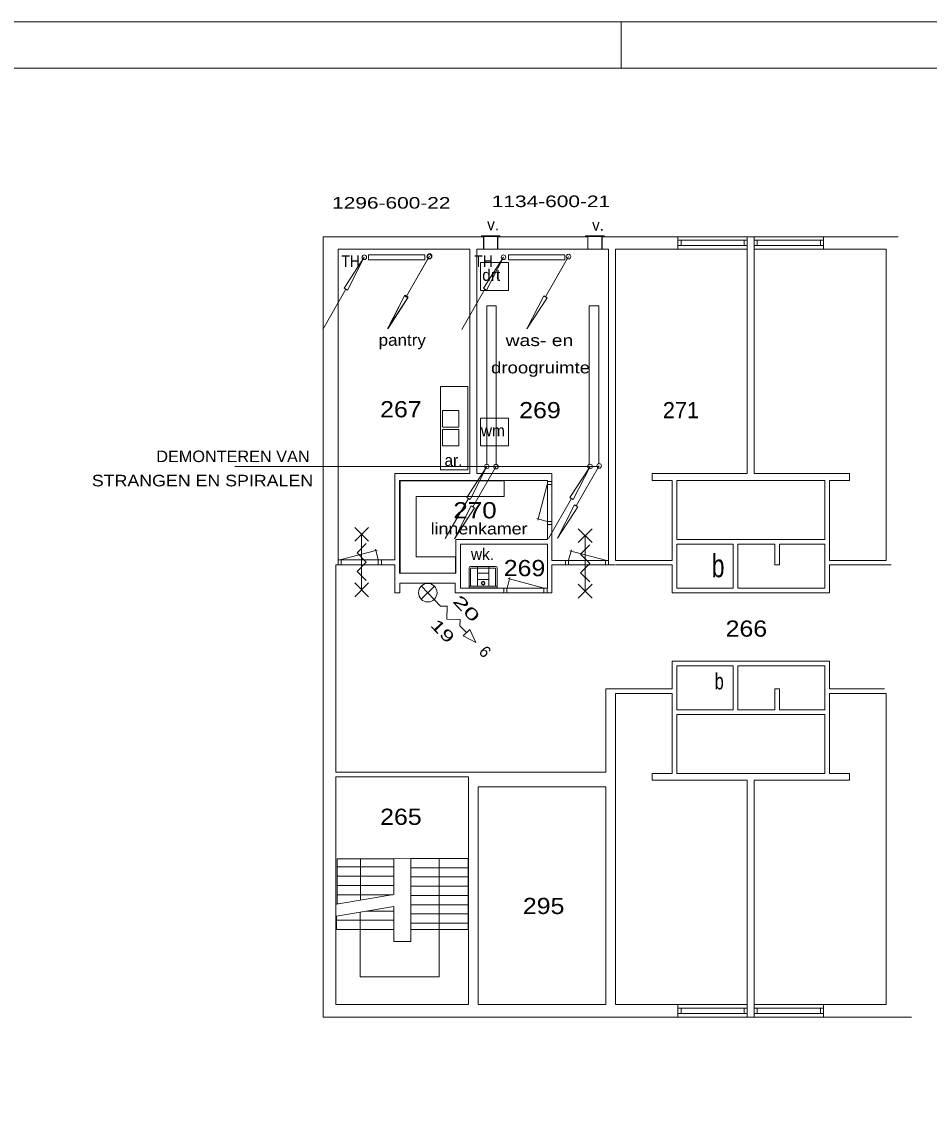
# Model space of a CAD drawing. Extents: x 295824 to 414724, y 24924 to 109024.
# Drawn here: x 338765 to 358386, y 85348 to 109024 of the extents above; entities that cross this region are included whole.
import ezdxf
from ezdxf.enums import TextEntityAlignment as Align

# ---------------------------------------------------------------- set-up
doc = ezdxf.new("R2010")
doc.units = 0
doc.header["$LTSCALE"] = 100
for name, color, linetype, lineweight in [('1', 7, 'Continuous', 13), ('16', 7, 'Continuous', 13), ('61', 7, 'Continuous', 13)]:
    doc.layers.add(name, color=color, linetype=linetype, lineweight=lineweight)

msp = doc.modelspace()

# ---------------------------------------------------------------- linework, layer by layer
at = {"layer": '1'}
msp.add_line((351723.6, 108023.8), (351723.6, 109023.8), dxfattribs=at)
for points in [[(414723.6, 109023.8), (304995.6, 109023.8), (295823.6, 109023.8)], [(304995.6, 25923.8), (413723.6, 25923.8), (413723.6, 108023.8), (304995.6, 108023.8)]]:
    msp.add_lwpolyline(points, dxfattribs=at)
at = {"layer": '16'}
for p, q in [((347576.1, 103948.9), (347076.1, 103082.9)), ((347582, 103960.7), (347082, 103094.7)), ((350586.2, 103948.9), (350086.2, 103082.9)), ((345270.5, 102377.2), (345770.5, 103243.2)), ((348280.7, 102377.2), (348780.7, 103243.2)), ((343368.4, 99410.3), (351252.5, 99410.3)), ((349017.9, 99408.9), (348517.9, 98542.9)), ((351249.9, 99425.5), (350749.9, 98559.5)), ((347920.8, 97854.5), (348420.8, 98720.5)), ((350152.8, 97854.5), (350652.8, 98720.5))]:
    msp.add_line(p, q, dxfattribs=at)
for points in [[(346170.5, 103936.2), (345806.5, 103222.2), (345734.5, 103264.2)], [(346260.1, 103883.5), (347476.8, 103883.5), (347476.8, 103990.7), (346260.1, 103990.7)], [(349180.7, 103936.2), (348816.7, 103222.2), (348744.7, 103264.2)], [(349287.8, 103883.5), (350504.5, 103883.5), (350504.5, 103990.7), (349287.8, 103990.7)], [(346676.1, 102389.9), (347040.1, 103103.9), (347112.1, 103061.9)], [(346682, 102401.7), (347046, 103115.7), (347118, 103073.7)], [(349686.2, 102389.9), (350050.2, 103103.9), (350122.2, 103061.9)], [(348820.8, 99413.5), (348456.8, 98699.5), (348384.8, 98741.5)], [(351052.8, 99413.5), (350688.8, 98699.5), (350616.8, 98741.5)], [(348117.9, 97849.9), (348481.9, 98563.9), (348553.9, 98521.9)], [(350349.9, 97866.5), (350713.9, 98580.5), (350785.9, 98538.5)]]:
    msp.add_lwpolyline(points, close=True, dxfattribs=at)
for points in [[(348821.9, 99450.9), (348821.9, 102882.9), (349024.4, 102882.9), (349024.4, 99462.8)], [(351037.1, 99450.9), (351037.1, 102882.9), (351239.5, 102882.9), (351239.5, 99462.8)]]:
    msp.add_lwpolyline(points, dxfattribs=at)
for centre in [(346170.5, 103935.8), (347576.1, 103949.2), (347582, 103961), (349180.7, 103935.8), (350586.2, 103949.2), (348820.8, 99413.2), (349017.9, 99409.2), (351052.8, 99413.2), (351249.9, 99425.8)]:
    msp.add_circle(centre, 50, dxfattribs=at)
at = {"layer": '61'}
for p, q in [((345284, 104378.8), (345284, 87509.4)), ((345654, 104378.8), (345284, 104378.8)), ((345284, 104378.8), (348747.5, 104378.8)), ((349101.1, 104400.3), (348702.8, 104400.3)), ((348702.8, 104400.3), (348702.8, 104385.2)), ((349101.1, 104385.2), (348702.8, 104385.2)), ((348747.5, 104378.8), (348747.5, 104110.1)), ((348753.1, 104385.2), (348753.1, 104110.9)), ((349051.8, 104385.2), (349051.8, 104110.9)), ((349058.2, 104378.8), (349058.2, 104110.4)), ((349058.2, 104378.8), (351001.2, 104378.8)), ((349101.1, 104400.3), (349101.1, 104385.2)), ((351354.8, 104400.3), (350956.5, 104400.3)), ((350956.5, 104400.3), (350956.5, 104385.2)), ((351354.8, 104385.2), (350956.5, 104385.2)), ((351001.2, 104378.8), (351001.2, 104110.4)), ((351006.8, 104385.2), (351006.8, 104110.9)), ((351305.5, 104385.2), (351305.5, 104110.9)), ((351311.9, 104378.8), (351311.9, 104108.8)), ((351311.9, 104378.8), (357714.4, 104378.8)), ((351354.8, 104400.3), (351354.8, 104385.2)), ((352953.9, 104111.8), (352953.9, 104381.8)), ((353020.7, 104190.1), (353020.7, 104303.9)), ((354385.7, 104189.5), (354385.7, 104303.5)), ((354669.2, 104190.4), (354669.2, 104304.4)), ((356033.5, 104190.1), (356033.5, 104303.8)), ((356102, 104111.8), (356102, 104382)), ((345604, 97284), (345604, 104108.8)), ((348604, 104110.1), (348747.5, 104110.1)), ((351454, 104108.8), (348604, 104108.8)), ((349051.8, 104110.9), (348753.1, 104110.9)), ((349058.2, 104110.4), (349204, 104110.4)), ((350854.5, 104110.4), (351001.2, 104110.4)), ((351305.5, 104110.9), (351006.8, 104110.9)), ((351604, 104108.8), (354454, 104108.8)), ((357454, 104108.8), (354604, 104108.8)), ((347864.1, 100620.5), (348214.1, 100620.5)), ((348215, 100618.8), (348215, 100268.8)), ((348214.1, 100266.4), (347864.1, 100266.4)), ((347864.1, 100212.3), (348214.1, 100212.3)), ((348215, 100210.6), (348215, 99860.6)), ((348214.1, 99858.2), (347864.1, 99858.2)), ((346929, 97103.8), (346929, 99108.8)), ((350127, 99024.6), (349919.9, 98251.8)), ((350228.5, 99090.8), (350127.6, 99090.8)), ((350226.5, 99023.8), (350128.9, 99023.8)), ((350226.9, 99090.8), (350130.2, 99090.8)), ((350126.4, 98226.2), (349899.5, 98286.9)), ((346262.8, 98096.2), (345962.8, 97796.2)), ((345962.8, 98096.2), (346262.8, 97796.2)), ((350226.2, 98223.8), (350127.6, 98223.8)), ((350226.5, 98156.8), (350127.6, 98156.8)), ((351099, 98066.6), (350799, 97766.6)), ((350799, 98066.6), (351099, 97766.6)), ((346112.8, 96746.2), (346112.8, 97946.2)), ((350949, 96716.6), (350949, 97916.6)), ((345672.2, 97398.6), (346444.9, 97605.7)), ((346470.6, 97399.3), (346409.8, 97626.1)), ((350588.1, 97384.9), (350648.9, 97611.8)), ((351386.5, 97384.3), (350613.8, 97591.3)), ((345673, 97284), (345673, 97398)), ((346473, 97284), (346473, 97398)), ((346540, 97284), (346540, 97398)), ((350518.8, 97284.8), (350518.8, 97383.7)), ((350585.8, 97285), (350585.8, 97383.7)), ((351385.8, 97284.8), (351385.8, 97383.7)), ((351452.8, 97284.8), (351452.8, 97383.7)), ((345554, 97284), (345604, 97284)), ((346829, 96683.8), (346829, 97284)), ((348149, 97103.8), (346929, 97103.8)), ((348435.5, 97215.8), (348435.5, 96800.8)), ((349010.5, 97250.8), (348470.5, 97250.8)), ((348470.5, 96840.8), (348470.5, 97200.8)), ((348485.5, 97215.8), (348995.5, 97215.8)), ((348620.5, 96825.8), (348620.5, 97250.8)), ((348860.5, 97109.1), (348620.5, 97109.1)), ((348860.5, 96825.8), (348860.5, 97250.8)), ((349010.5, 97200.8), (349010.5, 96840.8)), ((349045.5, 96800.8), (349045.5, 97215.8)), ((350229, 97283.8), (350229, 96683.8)), ((351600.1, 97283.8), (350229, 97283.8)), ((352829, 97283.8), (351615.2, 97283.8)), ((346262.8, 96896.2), (345962.8, 96596.2)), ((345962.8, 96896.2), (346262.8, 96596.2)), ((348139, 96893.8), (346939, 96893.8)), ((346939, 96683.8), (346939, 96893.8)), ((348139, 96683.8), (348139, 96893.8)), ((348860.5, 96967.5), (348620.5, 96967.5)), ((349258.4, 96783.9), (349319.2, 97010.8)), ((350056.8, 96783.3), (349284.1, 96990.3)), ((351099, 96866.6), (350799, 96566.6)), ((350799, 96866.6), (351099, 96566.6)), ((346939, 96683.8), (346829, 96683.8)), ((347687.6, 96823.5), (347399.9, 96545.7)), ((350229, 96683.8), (348139, 96683.8)), ((349035.5, 96825.8), (348445.5, 96825.8)), ((348445.5, 96790.8), (349035.5, 96790.8)), ((349189, 96683.8), (349189, 96782.7)), ((349256, 96684), (349256, 96782.7)), ((350056, 96683.8), (350056, 96782.7)), ((350123, 96683.8), (350123, 96782.7)), ((346088, 90036.5), (346088, 90933.3)), ((346809.5, 90933.3), (347175.2, 90938.7)), ((348415.1, 90938.7), (347175.2, 90938.7)), ((345586.7, 90755.8), (346809.5, 90755.8)), ((348415.1, 90738.7), (347175.2, 90738.7)), ((345586.7, 90555.8), (346809.5, 90555.8)), ((348415.1, 90538.7), (347175.2, 90538.7)), ((345586.7, 90355.8), (346809.5, 90355.8)), ((348415.1, 90338.7), (347175.2, 90338.7)), ((346811.5, 90159.7), (345571.7, 89948.5)), ((345586.7, 90155.8), (346788.3, 90155.8)), ((348415.1, 90138.7), (347175.2, 90138.7)), ((346811.5, 89903.1), (345571.7, 89691.9)), ((345586.7, 89955.8), (345614.2, 89955.8)), ((345586.7, 89955.8), (345614.2, 89955.8)), ((346219.8, 89802.3), (346811.5, 89802.3)), ((348415.1, 89938.7), (347175.2, 89938.7)), ((348415.1, 89738.7), (347175.2, 89738.7)), ((345571.7, 89691.9), (345571.7, 89402.3)), ((345571.7, 89602.3), (346811.5, 89602.3)), ((348415.1, 89538.7), (347175.2, 89538.7)), ((345571.7, 89402.3), (346811.5, 89402.3)), ((346811.5, 89402.3), (346811.5, 89144.4)), ((347175.2, 89402.3), (347175.2, 89144.4)), ((347175.2, 89144.4), (346811.5, 89144.4)), ((351604, 87779.4), (354454, 87779.4)), ((352953.9, 87509.2), (352953.9, 87779.2)), ((353020.7, 87587.5), (353020.7, 87701.3)), ((354385.7, 87586.9), (354385.7, 87700.9)), ((357454, 87779.4), (354604, 87779.4)), ((354669.2, 87587.8), (354669.2, 87701.8)), ((356033.5, 87587.5), (356033.5, 87701.2)), ((356102, 87509.2), (356102, 87779.4)), ((358007.8, 87509.4), (345284, 87509.4))]:
    msp.add_line(p, q, dxfattribs=at)
for points in [[(354454, 104378.8), (354454, 99258.8), (352394, 99258.8), (352394, 99108.8), (352829, 99108.8), (352829, 97383.8), (351604, 97383.8), (351604, 104108.8)], [(354604, 104378.8), (354604, 99258.8), (356664, 99258.8), (356664, 99108.8), (356229, 99108.8), (356229, 97383.8), (357454, 97383.8), (357454, 104108.8)], [(345604, 104108.8), (348454, 104108.8), (348454, 99258.8), (346829, 99258.8), (346829, 97398)], [(349204, 99258.8), (348604, 99258.8), (348604, 104108.8)], [(348604, 99258.8), (350229, 99258.8), (350229, 97383.8), (351454, 97383.8), (351454, 104108.8)], [(351311.9, 104108.8), (351454, 104108.8), (351454, 102933.8)], [(347815.9, 99340.5), (348410.6, 99340.5), (348410.6, 101140.5)], [(347815.9, 99340.5), (347815.9, 101140.5), (348410.6, 101140.5)], [(347865, 100268.8), (347865, 100618.8), (347864.1, 100620.5)], [(347865, 99860.6), (347865, 100210.6), (347864.1, 100212.3)], [(346929, 99108.8), (350129, 99108.8), (350129, 97833.8), (348149, 97833.8), (348149, 97103.8)], [(346212.8, 96946.2), (346012.8, 97146.2), (346212.8, 97346.2), (346012.8, 97546.2), (346212.8, 97746.2)], [(351049, 96916.6), (350849, 97116.6), (351049, 97316.6), (350849, 97516.6), (351049, 97716.6)], [(345606, 97284), (345606, 97398), (346829, 97398)], [(346829, 97284), (345606, 97284), (345606, 97398)], [(345554, 97284), (345554, 92804.4), (351394, 92804.4), (351394, 94604.4)], [(357567.7, 97283.8), (356229, 97283.8), (356229, 96683.8), (352829, 96683.8), (352829, 97283.8)], [(347404.8, 96828.5), (347821.6, 96396.9), (347963, 96394.4), (347958.1, 96111.6), (348240.9, 96106.7), (348238.4, 95965.2), (348377.4, 95821.4)], [(351394, 94604.4), (352829, 94604.4), (352829, 95204.4), (356229, 95204.4), (356229, 94604.4), (357421, 94604.4)], [(354454, 87511.6), (354454, 92629.4), (352394, 92629.4), (352394, 92779.4), (352829, 92779.4), (352829, 94504.4), (351604, 94504.4), (351604, 87779.4)], [(354604, 87509.4), (354604, 92629.4), (356664, 92629.4), (356664, 92779.4), (356229, 92779.4), (356229, 94504.4), (357454, 94504.4), (357454, 87779.4)], [(346809.5, 90159.4), (346809.5, 90933.3), (345586.7, 90933.3), (345586.7, 89955.8)], [(347786.9, 90938.7), (347786.9, 88378.1), (346084.1, 88378.1), (346084.1, 89779.2)], [(345571.7, 89402.3), (346811.5, 89402.3), (346811.5, 89903.1)]]:
    msp.add_lwpolyline(points, dxfattribs=at)
for points in [[(352953.9, 104189.9), (352953.9, 104303.9), (354452.5, 104303.9), (354452.5, 104189.9)], [(354604.1, 104190.1), (354604.1, 104304.1), (356103.5, 104304.1), (356103.5, 104190.1)], [(348686.3, 103220.9), (348686.3, 103820.9), (349286.3, 103820.9), (349286.3, 103220.9)], [(348686.3, 99857.2), (348686.3, 100457.2), (349286.3, 100457.2), (349286.3, 99857.2)], [(346943.7, 97108.4), (346943.7, 99102), (349194.4, 99102), (349194.4, 98761.9), (347293.7, 98761.9), (347293.7, 97459.5), (348143.9, 97459.5), (348143.9, 97108.4)], [(352929, 99108.8), (356129, 99108.8), (356129, 97833.8), (352929, 97833.8)], [(348249, 97733.8), (350129, 97733.8), (350129, 96783.8), (348249, 96783.8)], [(352929, 97733.8), (354149, 97733.8), (354149, 96783.8), (352929, 96783.8)], [(354249, 97733.8), (355049, 97733.8), (355049, 97283.8), (355149, 97283.8), (355149, 97733.8), (356129, 97733.8), (356129, 96783.8), (354249, 96783.8)], [(348305.4, 95751.9), (348449.3, 95890.9), (348585.8, 95605.6)], [(352929, 94154.4), (354149, 94154.4), (354149, 95104.4), (352929, 95104.4)], [(354249, 94154.4), (355049, 94154.4), (355049, 94604.4), (355149, 94604.4), (355149, 94154.4), (356129, 94154.4), (356129, 95104.4), (354249, 95104.4)], [(352929, 92779.4), (356129, 92779.4), (356129, 94054.4), (352929, 94054.4)], [(345554, 92704.4), (348424, 92704.4), (348424, 87779.4), (345554, 87779.4)], [(348634, 92484.4), (351394, 92484.4), (351394, 87779.4), (348634, 87779.4)], [(347175.2, 89402.3), (348415.1, 89402.3), (348415.1, 90938.7), (347175.2, 90938.7)], [(352953.9, 87587.3), (352953.9, 87701.3), (354452.5, 87701.3), (354452.5, 87587.3)], [(354602.9, 87587.5), (354602.9, 87701.5), (356102.2, 87701.5), (356102.2, 87587.5)]]:
    msp.add_lwpolyline(points, close=True, dxfattribs=at)
for centre, radius in [((347543.8, 96684.6), 200), ((348740.5, 96890.8), 40), ((348740.5, 96890.8), 30)]:
    msp.add_circle(centre, radius, dxfattribs=at)
for centre, radius, start, end in [((348470.5, 97215.8), 35, 90, 180), ((348485.5, 97200.8), 15, 90, 180), ((348995.5, 97200.8), 15, 0, 90), ((349010.5, 97215.8), 35, 0, 90), ((348485.5, 96840.8), 15, 180, 270), ((348995.5, 96840.8), 15, 270, 0), ((348445.5, 96815.8), 10, 90, 180), ((348445.5, 96800.8), 10, 180, 270), ((349035.5, 96815.8), 10, 0, 90), ((349035.5, 96800.8), 10, 270, 0)]:
    msp.add_arc(centre, radius, start, end, dxfattribs=at)

# ---------------------------------------------------------------- texts
at = {"layer": '16'}
for s, width, p in [('1296-600-22', 1.35, (345474.5, 104987.1)), ('1134-600-21', 1.35, (348927.7, 105020.4)), ('TH', 0.9, (345673.8, 103727.3)), ('TH', 0.9, (348548.4, 103727.3)), ('DEMONTEREN VAN', 1.05, (341671.2, 99507.1)), ('STRANGEN EN SPIRALEN', 1.15, (340277.8, 98982.8))]:
    msp.add_text(s, height=250, dxfattribs=dict(at, width=width)).set_placement(p)
at = {"layer": '61'}
for s, height, p in [('v.', 250, (348826.1, 104518.7)), ('v.', 250, (351095.4, 104508.6)), ('drt', 250, (348720.7, 103426.2)), ('271', 350, (352627.8, 100455.9)), ('wm', 250, (348691.3, 100065)), ('ar.', 250, (347904.3, 99422.9)), ('wk.', 250, (348476.2, 97391.7))]:
    msp.add_text(s, height=height, dxfattribs=at).set_placement(p)
for s, height, width, p in [('pantry', 250, 1.1, (346479.8, 102022.3)), ('was- en', 250, 1.25, (349226.4, 102016)), ('droogruimte', 250, 1.2, (348911.9, 101425.8)), ('267', 350, 1.15, (346512.8, 100475.6)), ('269', 350, 1.15, (349521.1, 100455.9)), ('270', 350, 1.2, (348095.8, 98291.6)), ('linnenkamer', 250, 1.15, (347605.2, 97943.9)), ('269', 350, 1.15, (349186.8, 97042.2)), ('266', 350, 1.15, (353984.5, 95733.8)), ('265', 350, 1.15, (346512.8, 91665.8)), ('295', 350, 1.15, (349599.8, 89737.6))]:
    msp.add_text(s, height=height, dxfattribs=dict(at, width=width)).set_placement(p)
at = {"layer": '61', "width": 0.75}
for height, p in [(500, (353822, 97018.3)), (350, (353846.1, 94593.8))]:
    msp.add_text('b', height=height, dxfattribs=at).set_placement(p, align=Align.CENTER)
at = {"layer": '61'}
for s, width, p in [('20', 1.75, (348063, 96490.3)), ('19', 1.5, (347581.6, 95970.2))]:
    msp.add_text(s, height=250, rotation=314, dxfattribs=dict(at, width=width)).set_placement(p)
msp.add_text('6', height=250, rotation=314, dxfattribs=at).set_placement((348627.9, 95390.3))

doc.saveas('drawing.dxf')
